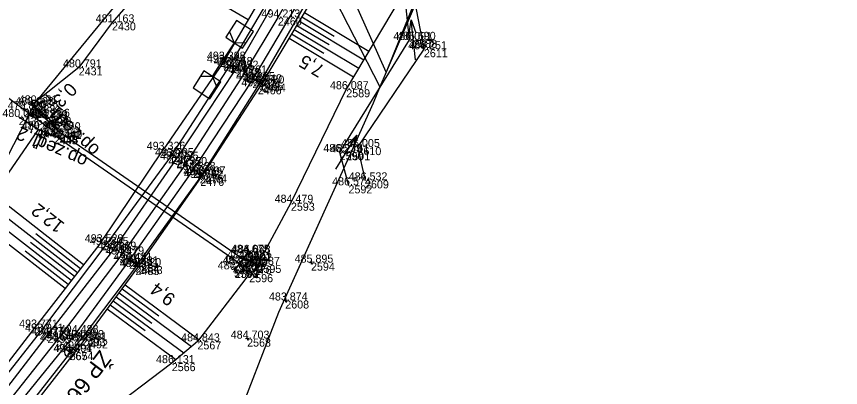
# Model space of a CAD drawing. Extents: x -1234191 to 23050, y -1290331 to -741191.
# Drawn here: x -864731.5 to -864608, y -1102915.1 to -1102859.5 of the extents above; entities that cross this region are included whole.
import ezdxf

# ---------------------------------------------------------------- set-up
doc = ezdxf.new("R2010")
doc.units = 0
for name, color, linetype in [('Vrstva 1', 7, 'Continuous'), ('Vrstva 13', 7, 'Continuous'), ('Vrstva 19', 7, 'Continuous'), ('Vrstva 4', 7, 'Continuous'), ('Vrstva 48', 7, 'Continuous'), ('Vrstva 49', 7, 'Continuous'), ('Vrstva 50', 7, 'Continuous'), ('Vrstva 53', 7, 'Continuous'), ('Vrstva 55', 7, 'Continuous'), ('Vrstva 58', 7, 'Continuous'), ('Vrstva 60', 7, 'Continuous'), ('Vrstva 61', 7, 'Continuous'), ('Vrstva 63', 7, 'Continuous'), ('Vrstva 7', 7, 'Continuous')]:
    doc.layers.add(name, color=color, linetype=linetype)

msp = doc.modelspace()

# ---------------------------------------------------------------- linework, layer by layer
at = {"layer": 'Vrstva 1'}
msp.add_lwpolyline([(-864682.21, -1102841.27), (-864687.29, -1102850.82), (-864692.33, -1102859.68), (-864697.4, -1102868.06), (-864706.3, -1102881.78), (-864715.74, -1102895.17), (-864725.57, -1102908.17), (-864735.83, -1102921.05), (-864737.97, -1102923.69), (-864746.17, -1102933.69), (-864756.55, -1102946.22), (-864772.27, -1102965.21), (-864787.36, -1102983.61), (-864800.07, -1102999.57)], dxfattribs=at)
at = {"layer": 'Vrstva 13'}
for p, q in [((-864724.79, -1102874.28), (-864726.15, -1102875.74)), ((-864727.28, -1102874.75), (-864726.88, -1102874.55)), ((-864727.28, -1102874.75), (-864727.2, -1102874.76)), ((-864727.2, -1102874.76), (-864725.27, -1102876.56)), ((-864727.85, -1102878.83), (-864727.06, -1102877))]:
    msp.add_line(p, q, dxfattribs=at)
for points in [[(-864725.27, -1102876.56), (-864725.35, -1102876.68), (-864727.28, -1102874.75)], [(-864727.2, -1102874.76), (-864726.88, -1102874.55), (-864725.27, -1102876.56), (-864725.35, -1102876.68)], [(-864726.03, -1102875.17), (-864726.15, -1102875.74), (-864725.59, -1102875.58)], [(-864725.94, -1102877.48), (-864728.29, -1102876.47), (-864728.3, -1102876.41), (-864725.85, -1102877.35), (-864725.94, -1102877.48)], [(-864726.98, -1102877.57), (-864727.06, -1102877), (-864727.53, -1102877.34)]]:
    msp.add_lwpolyline(points, dxfattribs=at)
at = {"layer": 'Vrstva 19'}
for p, q in [((-864766.6, -1102846.79), (-864725.6, -1102877.02)), ((-864725.35, -1102876.68), (-864725.27, -1102876.56)), ((-864697.57, -1102895.85), (-864725.35, -1102876.68)), ((-864725.35, -1102876.68), (-864725.35, -1102876.69)), ((-864697.57, -1102895.85), (-864725.35, -1102876.69)), ((-864725.85, -1102877.35), (-864725.94, -1102877.48)), ((-864698.11, -1102896.53), (-864725.85, -1102877.35)), ((-864725.85, -1102877.35), (-864725.85, -1102877.36)), ((-864698.1, -1102896.53), (-864725.85, -1102877.36)), ((-864696.79, -1102894.98), (-864698.81, -1102897.48)), ((-864698.8, -1102897.48), (-864696.79, -1102894.98)), ((-864696.79, -1102894.98), (-864696.79, -1102894.98)), ((-864698.11, -1102896.53), (-864698.21, -1102896.68)), ((-864698.11, -1102896.53), (-864698.1, -1102896.53)), ((-864696.63, -1102898.12), (-864698.11, -1102896.53)), ((-864698.1, -1102896.53), (-864697.57, -1102895.85)), ((-864697.49, -1102895.77), (-864697.57, -1102895.85)), ((-864697.57, -1102895.85), (-864697.57, -1102895.85)), ((-864697.57, -1102895.85), (-864695.39, -1102896.73)), ((-864695.39, -1102896.73), (-864697.49, -1102895.77)), ((-864698.81, -1102897.48), (-864698.8, -1102897.48)), ((-864698.21, -1102896.68), (-864696.63, -1102898.12))]:
    msp.add_line(p, q, dxfattribs=at)
for points in [[(-864725.27, -1102876.56), (-864725.94, -1102877.48)], [(-864725.85, -1102877.36), (-864725.35, -1102876.69)], [(-864697.49, -1102895.77), (-864696.91, -1102894.9), (-864696.79, -1102894.98)], [(-864698.21, -1102896.68), (-864698.92, -1102897.39), (-864698.8, -1102897.48)]]:
    msp.add_lwpolyline(points, dxfattribs=at)
at = {"layer": 'Vrstva 4'}
for points in [[(-864718.08, -1102893.74), (-864708.31, -1102880.42), (-864699.48, -1102866.8), (-864689.49, -1102849.9), (-864680.3, -1102831.93)], [(-864819.07, -1103021.91), (-864810.52, -1103010.02), (-864801.81, -1102998.6), (-864788.83, -1102982.45), (-864773.71, -1102964.13), (-864757.66, -1102945.31), (-864747.28, -1102932.75), (-864736.85, -1102920.15), (-864726.88, -1102907.24), (-864716.92, -1102894.44), (-864707.57, -1102880.97), (-864698.6, -1102867.35), (-864688.65, -1102850.07), (-864679.31, -1102832.31)], [(-864722.59, -1102906.94), (-864714.62, -1102896.1), (-864705.04, -1102882.52), (-864696.16, -1102869.06), (-864685.87, -1102851.67), (-864676.73, -1102833.65)], [(-864713.68, -1102897.05), (-864703.97, -1102883.7), (-864695.35, -1102869.99), (-864684.84, -1102851.86), (-864675.87, -1102834.17)], [(-864748.12, -1102932.02), (-864737.77, -1102919.21), (-864727.89, -1102906.72), (-864718.08, -1102893.74)], [(-864713.68, -1102897.05), (-864721.76, -1102907.69)], [(-864771.24, -1102966.15), (-864755.24, -1102946.97), (-864745.12, -1102934.48), (-864734.72, -1102921.84), (-864722.59, -1102906.94)], [(-864743.68, -1102935.62), (-864733.15, -1102922.25), (-864721.76, -1102907.69)]]:
    msp.add_lwpolyline(points, dxfattribs=at)
at = {"layer": 'Vrstva 48'}
for p, q in [((-864696.78, -1102860.02), (-864710.06, -1102852.26)), ((-864688.35, -1102858.93), (-864678.69, -1102864.71)), ((-864689.12, -1102860.22), (-864679.45, -1102866)), ((-864688.74, -1102859.57), (-864683.9, -1102862.46)), ((-864689.89, -1102861.5), (-864680.22, -1102867.29)), ((-864689.51, -1102860.86), (-864684.67, -1102863.75)), ((-864690.66, -1102862.79), (-864680.98, -1102868.58)), ((-864690.28, -1102862.15), (-864685.44, -1102865.04)), ((-864728.5, -1102873.38), (-864728.58, -1102873.49)), ((-864727.89, -1102873.81), (-864727.97, -1102873.92)), ((-864727.29, -1102874.25), (-864727.49, -1102874.54)), ((-864729.72, -1102875.55), (-864729.7, -1102875.53)), ((-864729.08, -1102875.95), (-864729.08, -1102875.94)), ((-864728.45, -1102876.36), (-864728.43, -1102876.32)), ((-864721.48, -1102896.72), (-864735.05, -1102886.16)), ((-864722.4, -1102897.9), (-864735.69, -1102887.57)), ((-864723.32, -1102899.09), (-864736.33, -1102888.97)), ((-864724.24, -1102900.27), (-864736.96, -1102890.38)), ((-864721.94, -1102897.31), (-864728.65, -1102892.09)), ((-864722.86, -1102898.49), (-864729.43, -1102893.38)), ((-864723.78, -1102899.68), (-864730.21, -1102894.68)), ((-864715.26, -1102899.71), (-864704.17, -1102907.88)), ((-864716.15, -1102900.92), (-864705.28, -1102908.93)), ((-864715.7, -1102900.31), (-864710.2, -1102904.37)), ((-864717.48, -1102902.73), (-864712.26, -1102906.57)), ((-864717.04, -1102902.12), (-864706.46, -1102909.92)), ((-864716.59, -1102901.52), (-864711.23, -1102905.47)), ((-864717.93, -1102903.33), (-864707.64, -1102910.92))]:
    msp.add_line(p, q, dxfattribs=at)
at = {"layer": 'Vrstva 49'}
for p, q in [((-864729.28, -1102872.81), (-864727.28, -1102874.75)), ((-864730.22, -1102873.59), (-864730.58, -1102873.24)), ((-864730.22, -1102873.24), (-864730.58, -1102873.59)), ((-864728.3, -1102876.41), (-864731.2, -1102874.59)), ((-864687.13, -1102896.34), (-864687.62, -1102896.43)), ((-864687.42, -1102896.14), (-864687.33, -1102896.63)), ((-864690.98, -1102902.01), (-864691.47, -1102902.1)), ((-864691.27, -1102901.81), (-864691.18, -1102902.3)), ((-864697, -1102907.53), (-864696.91, -1102908.02)), ((-864696.71, -1102907.73), (-864697.2, -1102907.81))]:
    msp.add_line(p, q, dxfattribs=at)
for points in [[(-864681.8, -1102831.96), (-864690.53, -1102849.31), (-864700.52, -1102866.44), (-864709.56, -1102879.49)], [(-864696.65, -1102832.92), (-864706.57, -1102848.27), (-864717.21, -1102860.41), (-864722.2, -1102867.15), (-864729.28, -1102872.81)], [(-864713.19, -1102896.91), (-864703.54, -1102883.19), (-864694.72, -1102869.57), (-864684.76, -1102852.92), (-864675.25, -1102834.44)], [(-864673.84, -1102856.53), (-864682.08, -1102870.42), (-864690.38, -1102887.42), (-864695.39, -1102896.73)], [(-864727.28, -1102874.75), (-864726.88, -1102874.55), (-864729.28, -1102872.81)], [(-864728.3, -1102876.41), (-864728.29, -1102876.47), (-864731.2, -1102874.59)], [(-864726.88, -1102874.55), (-864725.27, -1102876.56), (-864725.94, -1102877.48), (-864728.29, -1102876.47)], [(-864728.29, -1102876.47), (-864735.05, -1102886.17), (-864740.93, -1102899.13), (-864750.93, -1102912.52)], [(-864718.85, -1102893.34), (-864709.56, -1102879.49)], [(-864718.85, -1102893.34), (-864728.78, -1102906.11), (-864738.85, -1102919.08)], [(-864695.39, -1102896.73), (-864697.49, -1102895.77), (-864696.91, -1102894.9), (-864696.79, -1102894.98), (-864696.79, -1102894.98), (-864698.81, -1102897.48), (-864698.8, -1102897.48), (-864698.92, -1102897.39), (-864698.21, -1102896.68), (-864696.63, -1102898.12)], [(-864743.11, -1102936.38), (-864733.13, -1102923.08), (-864721.39, -1102908.03), (-864713.19, -1102896.91)], [(-864696.63, -1102898.12), (-864704.4, -1102908.18), (-864708.25, -1102911.44), (-864718.78, -1102919.45)]]:
    msp.add_lwpolyline(points, dxfattribs=at)
at = {"layer": 'Vrstva 50'}
for points in [[(-864673.32, -1102856.72), (-864672.67, -1102863.05), (-864683.08, -1102879.83)], [(-864671.84, -1102857.18), (-864670.44, -1102864.43)], [(-864670.44, -1102864.43), (-864680.4, -1102879.09), (-864679.27, -1102884.07)], [(-864683.08, -1102879.83), (-864681.75, -1102884.82)]]:
    msp.add_lwpolyline(points, dxfattribs=at)
at = {"layer": 'Vrstva 53'}
msp.add_line((-864728.85, -1102872.59), (-864728.81, -1102872.5), dxfattribs=at)
for points in [[(-864635.49, -1102733.5), (-864648.81, -1102800.46), (-864672.22, -1102858.78), (-864676.09, -1102867.88), (-864682.21, -1102854.19), (-864688.16, -1102846.44), (-864691.61, -1102825.91), (-864690.2, -1102823.4), (-864687.83, -1102820.97), (-864676.39, -1102798.67), (-864665.19, -1102755.33)], [(-864889.03, -1103323.28), (-864892.77, -1103263.78), (-864892.91, -1103184.37), (-864883.42, -1103119.48), (-864874.29, -1103087.16), (-864855.71, -1103052.53), (-864814.57, -1102995.09), (-864799.32, -1102988.77), (-864779.65, -1102957.8), (-864778.43, -1102951.42), (-864757.64, -1102926.36), (-864755.77, -1102924.22), (-864753.95, -1102921.47), (-864728.77, -1102872.58), (-864694.07, -1102830.31)], [(-864694.07, -1102830.31), (-864690.75, -1102847.15), (-864684.74, -1102855.05), (-864677.03, -1102870.08), (-864678.05, -1102872.49), (-864681.46, -1102880.03), (-864685.19, -1102888.26), (-864686.8, -1102891.82), (-864692.25, -1102903.86), (-864699.08, -1102921.54), (-864699.89, -1102923.65), (-864702.16, -1102929.53), (-864722.42, -1102960.74), (-864750.87, -1102982.07), (-864779.87, -1103011.49)]]:
    msp.add_lwpolyline(points, dxfattribs=at)
msp.add_circle((-864728.83, -1102872.54), 0.499, dxfattribs=at)
at = {"layer": 'Vrstva 55'}
for points in [[(-864685.34, -1102369.7), (-864652.19, -1102431.45), (-864635.26, -1102468.98), (-864625.8, -1102502.03), (-864631.68, -1102514.84), (-864613.23, -1102518.45), (-864607.97, -1102568.96), (-864611.13, -1102641.68), (-864611.4, -1102663.26), (-864622.78, -1102711.51), (-864635.49, -1102733.5), (-864648.81, -1102800.46), (-864676.09, -1102867.88), (-864677.03, -1102870.08)], [(-864677.03, -1102870.08), (-864678.05, -1102872.49), (-864681.46, -1102880.03), (-864685.19, -1102888.26), (-864692.25, -1102903.86), (-864699.08, -1102921.54), (-864702.16, -1102929.53), (-864722.42, -1102960.74), (-864750.87, -1102982.07), (-864779.87, -1103011.49), (-864808.83, -1103051.1), (-864846.52, -1103114.38), (-864836.8, -1103132.5), (-864838.87, -1103147.22), (-864863.34, -1103166.58), (-864871.29, -1103216.08), (-864869.74, -1103303.4), (-864855.1, -1103331.53)]]:
    msp.add_lwpolyline(points, dxfattribs=at)
at = {"layer": 'Vrstva 58'}
for p, q in [((-864671.72, -1102866), (-864672.34, -1102860.03)), ((-864683.66, -1102882.4), (-864680.48, -1102877.32))]:
    msp.add_line(p, q, dxfattribs=at)
for points in [[(-864672.63, -1102862.07), (-864672.34, -1102860.03), (-864671.64, -1102861.97)], [(-864681.97, -1102878.75), (-864680.48, -1102877.32), (-864681.12, -1102879.28)]]:
    msp.add_lwpolyline(points, dxfattribs=at)
at = {"layer": 'Vrstva 60'}
for p, q in [((-864717.21, -1102860.41), (-864717.21, -1102860.41)), ((-864692.33, -1102859.68), (-864692.33, -1102859.68)), ((-864672.67, -1102863.05), (-864672.67, -1102863.05)), ((-864672.03, -1102863.02), (-864672.03, -1102863.02)), ((-864670.44, -1102864.43), (-864670.44, -1102864.43)), ((-864700.53, -1102865.99), (-864700.53, -1102865.99)), ((-864700.52, -1102866.44), (-864700.52, -1102866.44)), ((-864699.48, -1102866.8), (-864699.48, -1102866.8)), ((-864722.2, -1102867.15), (-864722.2, -1102867.15)), ((-864698.6, -1102867.35), (-864698.6, -1102867.35)), ((-864697.4, -1102868.06), (-864697.4, -1102868.06)), ((-864696.16, -1102869.06), (-864696.16, -1102869.06)), ((-864695.08, -1102869.38), (-864695.08, -1102869.38)), ((-864695.35, -1102869.99), (-864695.35, -1102869.99)), ((-864694.72, -1102869.57), (-864694.72, -1102869.57)), ((-864682.08, -1102870.42), (-864682.08, -1102870.42)), ((-864729.28, -1102872.81), (-864729.28, -1102872.81)), ((-864728.83, -1102872.54), (-864728.83, -1102872.54)), ((-864730.4, -1102873.42), (-864730.4, -1102873.42)), ((-864731.2, -1102874.59), (-864731.2, -1102874.59)), ((-864727.28, -1102874.75), (-864727.28, -1102874.75)), ((-864727.2, -1102874.76), (-864727.2, -1102874.76)), ((-864726.88, -1102874.55), (-864726.88, -1102874.55)), ((-864728.3, -1102876.41), (-864728.3, -1102876.41)), ((-864728.29, -1102876.47), (-864728.29, -1102876.47)), ((-864725.35, -1102876.68), (-864725.35, -1102876.68)), ((-864725.35, -1102876.69), (-864725.35, -1102876.69)), ((-864725.27, -1102876.56), (-864725.27, -1102876.56)), ((-864725.94, -1102877.48), (-864725.94, -1102877.48)), ((-864725.85, -1102877.35), (-864725.85, -1102877.35)), ((-864725.85, -1102877.36), (-864725.85, -1102877.36)), ((-864680.4, -1102879.09), (-864680.4, -1102879.09)), ((-864709.56, -1102879.49), (-864709.56, -1102879.49)), ((-864708.31, -1102880.42), (-864708.31, -1102880.42)), ((-864683.08, -1102879.83), (-864683.08, -1102879.83)), ((-864682.07, -1102879.86), (-864682.07, -1102879.86)), ((-864707.57, -1102880.97), (-864707.57, -1102880.97)), ((-864706.3, -1102881.78), (-864706.3, -1102881.78)), ((-864705.04, -1102882.52), (-864705.04, -1102882.52)), ((-864704.05, -1102883.33), (-864704.05, -1102883.33)), ((-864703.97, -1102883.7), (-864703.97, -1102883.7)), ((-864703.54, -1102883.19), (-864703.54, -1102883.19)), ((-864679.27, -1102884.07), (-864679.27, -1102884.07)), ((-864681.75, -1102884.82), (-864681.75, -1102884.82)), ((-864690.38, -1102887.42), (-864690.38, -1102887.42)), ((-864718.85, -1102893.34), (-864718.85, -1102893.34)), ((-864718.08, -1102893.74), (-864718.08, -1102893.74)), ((-864716.92, -1102894.44), (-864716.92, -1102894.44)), ((-864715.74, -1102895.17), (-864715.74, -1102895.17)), ((-864696.91, -1102894.9), (-864696.91, -1102894.9)), ((-864696.79, -1102894.98), (-864696.79, -1102894.98)), ((-864696.79, -1102894.98), (-864696.79, -1102894.98)), ((-864714.62, -1102896.1), (-864714.62, -1102896.1)), ((-864698.11, -1102896.53), (-864698.11, -1102896.53)), ((-864698.1, -1102896.53), (-864698.1, -1102896.53)), ((-864697.57, -1102895.85), (-864697.57, -1102895.85)), ((-864697.57, -1102895.85), (-864697.57, -1102895.85)), ((-864697.49, -1102895.77), (-864697.49, -1102895.77)), ((-864687.37, -1102896.39), (-864687.37, -1102896.39)), ((-864713.68, -1102896.65), (-864713.68, -1102896.65)), ((-864713.68, -1102897.05), (-864713.68, -1102897.05)), ((-864713.19, -1102896.91), (-864713.19, -1102896.91)), ((-864698.92, -1102897.39), (-864698.92, -1102897.39)), ((-864698.81, -1102897.48), (-864698.81, -1102897.48)), ((-864698.8, -1102897.48), (-864698.8, -1102897.48)), ((-864698.21, -1102896.68), (-864698.21, -1102896.68)), ((-864695.39, -1102896.73), (-864695.39, -1102896.73)), ((-864696.63, -1102898.12), (-864696.63, -1102898.12)), ((-864691.23, -1102902.06), (-864691.23, -1102902.06)), ((-864728.78, -1102906.11), (-864728.78, -1102906.11)), ((-864727.89, -1102906.72), (-864727.89, -1102906.72)), ((-864726.88, -1102907.24), (-864726.88, -1102907.24)), ((-864722.59, -1102906.94), (-864722.59, -1102906.94)), ((-864721.76, -1102907.69), (-864721.76, -1102907.69)), ((-864725.57, -1102908.17), (-864725.57, -1102908.17)), ((-864721.39, -1102908.03), (-864721.39, -1102908.03)), ((-864704.4, -1102908.18), (-864704.4, -1102908.18)), ((-864696.95, -1102907.77), (-864696.95, -1102907.77)), ((-864723.6, -1102909.79), (-864723.6, -1102909.79)), ((-864723.55, -1102909.79), (-864723.55, -1102909.79)), ((-864708.25, -1102911.44), (-864708.25, -1102911.44))]:
    msp.add_line(p, q, dxfattribs=at)
at = {"layer": 'Vrstva 63'}
msp.add_line((-864723.6, -1102909.79), (-864723.5, -1102909.79), dxfattribs=at)
msp.add_circle((-864723.55, -1102909.79), 0.756, dxfattribs=at)
at = {"layer": 'Vrstva 7'}
for p, q in [((-864698.9, -1102863.47), (-864700.53, -1102865.99)), ((-864702.16, -1102868.5), (-864700.53, -1102865.99)), ((-864700.11, -1102866.26), (-864700.95, -1102865.71)), ((-864700.95, -1102865.71), (-864700.11, -1102866.26)), ((-864694.65, -1102869.64), (-864695.51, -1102869.12)), ((-864694.82, -1102868.95), (-864695.34, -1102869.81)), ((-864703.77, -1102882.92), (-864704.34, -1102883.74)), ((-864703.65, -1102883.62), (-864704.46, -1102883.04)), ((-864713.28, -1102896.95), (-864714.08, -1102896.34)), ((-864713.38, -1102896.25), (-864713.98, -1102897.04)), ((-864723.21, -1102910.1), (-864723.99, -1102909.48)), ((-864723.29, -1102909.4), (-864723.91, -1102910.18))]:
    msp.add_line(p, q, dxfattribs=at)
for points in [[(-864698.9, -1102863.47), (-864697.64, -1102864.29), (-864696, -1102861.77), (-864698.52, -1102860.14), (-864700.15, -1102862.65), (-864698.9, -1102863.47)], [(-864699.61, -1102861.81), (-864698.9, -1102863.47), (-864697.09, -1102863.44)], [(-864702.16, -1102868.5), (-864703.42, -1102867.69), (-864705.05, -1102870.2), (-864702.53, -1102871.84), (-864700.9, -1102869.32), (-864702.16, -1102868.5)], [(-864701.45, -1102870.16), (-864702.16, -1102868.5), (-864703.96, -1102868.53)]]:
    msp.add_lwpolyline(points, dxfattribs=at)

# ---------------------------------------------------------------- texts
at = {"layer": 'Vrstva 13'}
for s, rotation, p in [('1,2', 137.1166, (-864724.44, -1102873.62)), ('op.zeď', 137.1166, (-864718.93, -1102879.26)), ('1,2', 156.6954, (-864727.56, -1102877.44)), ('op.zeď', 156.6954, (-864720.7, -1102880.49))]:
    msp.add_text(s, height=2, rotation=rotation, dxfattribs=at).set_placement(p)
at = {"layer": 'Vrstva 48'}
for s, rotation, p in [('7,5', 149.3258, (-864685.18, -1102867.06)), ('0,3', 225.9735, (-864723.69, -1102869.28)), ('12,2', 142.1331, (-864724.18, -1102890.57)), ('9,4', 142.3358, (-864707.53, -1102901.48))]:
    msp.add_text(s, height=2, rotation=rotation, dxfattribs=at).set_placement(p)
at = {"layer": 'Vrstva 60'}
for s, p in [('2430', (-864717.21, -1102861.61)), ('2460', (-864692.33, -1102860.88)), ('2587', (-864672.67, -1102864.25)), ('2588', (-864672.03, -1102864.22)), ('2611', (-864670.44, -1102865.63)), ('2471', (-864700.53, -1102867.19)), ('2470', (-864700.52, -1102867.64)), ('2469', (-864699.48, -1102868)), ('2431', (-864722.2, -1102868.35)), ('2468', (-864698.6, -1102868.55)), ('2462', (-864697.4, -1102869.27)), ('2467', (-864696.16, -1102870.26)), ('2465', (-864695.08, -1102870.58)), ('2466', (-864695.35, -1102871.19)), ('2464', (-864694.72, -1102870.77)), ('2589', (-864682.08, -1102871.62)), ('2433', (-864729.28, -1102874.01)), ('2432', (-864728.83, -1102873.74)), ('2434', (-864730.4, -1102874.62)), ('2435', (-864731.2, -1102875.79)), ('2437', (-864727.28, -1102875.95)), ('2438', (-864727.2, -1102875.96)), ('2439', (-864726.88, -1102875.75)), ('2447', (-864728.3, -1102877.61)), ('2446', (-864728.29, -1102877.67)), ('2442', (-864725.35, -1102877.88)), ('2441', (-864725.35, -1102877.89)), ('2440', (-864725.27, -1102877.76)), ('2445', (-864725.94, -1102878.68)), ('2443', (-864725.85, -1102878.55)), ('2444', (-864725.85, -1102878.56)), ('2610', (-864680.4, -1102880.29)), ('2480', (-864709.56, -1102880.69)), ('2479', (-864708.31, -1102881.62)), ('2590', (-864683.08, -1102881.03)), ('2591', (-864682.07, -1102881.06)), ('2478', (-864707.57, -1102882.17)), ('2472', (-864706.3, -1102882.98)), ('2477', (-864705.04, -1102883.72)), ('2475', (-864704.05, -1102884.53)), ('2476', (-864703.97, -1102884.9)), ('2474', (-864703.54, -1102884.39)), ('2609', (-864679.27, -1102885.27)), ('2592', (-864681.75, -1102886.02)), ('2593', (-864690.38, -1102888.62)), ('2489', (-864718.85, -1102894.54)), ('2488', (-864718.08, -1102894.94)), ('2487', (-864716.92, -1102895.64)), ('2481', (-864715.74, -1102896.37)), ('5701', (-864696.91, -1102896.1)), ('2601', (-864696.79, -1102896.18)), ('2602', (-864696.79, -1102896.18)), ('2486', (-864714.62, -1102897.3)), ('2604', (-864698.11, -1102897.73)), ('2605', (-864698.1, -1102897.73)), ('2606', (-864697.57, -1102897.05)), ('2607', (-864697.57, -1102897.05)), ('2600', (-864697.49, -1102896.97)), ('2594', (-864687.37, -1102897.59)), ('2484', (-864713.68, -1102897.85)), ('2485', (-864713.68, -1102898.25)), ('2483', (-864713.19, -1102898.11)), ('5700', (-864698.92, -1102898.59)), ('2597', (-864698.81, -1102898.68)), ('2598', (-864698.8, -1102898.68)), ('2599', (-864698.21, -1102897.88)), ('2595', (-864695.39, -1102897.93)), ('2596', (-864696.63, -1102899.32)), ('2608', (-864691.23, -1102903.26)), ('2497', (-864728.78, -1102907.31)), ('2496', (-864727.89, -1102907.92)), ('2495', (-864726.88, -1102908.44)), ('2494', (-864722.59, -1102908.14)), ('2493', (-864721.76, -1102908.89)), ('2490', (-864725.57, -1102909.37)), ('2492', (-864721.39, -1102909.23)), ('2567', (-864704.4, -1102909.38)), ('2568', (-864696.95, -1102908.97)), ('2674', (-864723.6, -1102910.99)), ('665', (-864723.55, -1102910.99)), ('2566', (-864708.25, -1102912.64))]:
    msp.add_text(s, height=1.2, dxfattribs=at).set_placement(p)
at = {"layer": 'Vrstva 61'}
for s, p in [('481.163', (-864719.66, -1102860.41)), ('494.213', (-864694.79, -1102859.68)), ('486.091', (-864675.02, -1102863.05)), ('485.690', (-864674.48, -1102863.02)), ('486.251', (-864672.79, -1102864.43)), ('493.398', (-864702.98, -1102865.99)), ('493.445', (-864702.98, -1102866.44)), ('493.658', (-864701.93, -1102866.8)), ('480.791', (-864724.56, -1102867.15)), ('494.052', (-864701.05, -1102867.35)), ('494.261', (-864699.76, -1102868.06)), ('494.265', (-864698.61, -1102869.06)), ('493.708', (-864697.81, -1102869.99)), ('494.040', (-864697.53, -1102869.38)), ('493.580', (-864697.17, -1102869.57)), ('486.087', (-864684.53, -1102870.42)), ('480.003', (-864731.73, -1102872.81)), ('480.531', (-864731.19, -1102872.54)), ('479.820', (-864732.85, -1102873.42)), ('480.058', (-864733.65, -1102874.59)), ('480.219', (-864729.66, -1102874.76)), ('479.881', (-864729.63, -1102874.75)), ('480.266', (-864729.33, -1102874.55)), ('479.906', (-864730.75, -1102876.41)), ('480.277', (-864730.74, -1102876.47)), ('479.983', (-864727.81, -1102876.68)), ('481.383', (-864727.81, -1102876.69)), ('481.950', (-864727.72, -1102876.56)), ('481.855', (-864728.4, -1102877.48)), ('479.956', (-864728.3, -1102877.35)), ('481.356', (-864728.3, -1102877.36)), ('486.005', (-864682.85, -1102879.09)), ('493.326', (-864712.01, -1102879.49)), ('493.705', (-864710.76, -1102880.42)), ('486.233', (-864685.53, -1102879.83)), ('485.741', (-864684.43, -1102879.86)), ('494.095', (-864710.02, -1102880.97)), ('494.350', (-864708.75, -1102881.78)), ('494.328', (-864707.49, -1102882.52)), ('494.019', (-864706.51, -1102883.33)), ('493.682', (-864706.42, -1102883.7)), ('493.607', (-864705.99, -1102883.19)), ('486.532', (-864681.72, -1102884.07)), ('486.574', (-864684.2, -1102884.82)), ('484.479', (-864692.83, -1102887.42)), ('493.529', (-864721.3, -1102893.34)), ('493.805', (-864720.54, -1102893.74)), ('494.269', (-864719.37, -1102894.44)), ('494.479', (-864718.2, -1102895.17)), ('484.675', (-864699.37, -1102894.9)), ('485.088', (-864699.24, -1102894.98)), ('484.688', (-864699.24, -1102894.98)), ('494.431', (-864716.98, -1102896.1)), ('482.525', (-864700.56, -1102896.53)), ('484.195', (-864700.56, -1102896.53)), ('484.224', (-864700.02, -1102895.85)), ('482.554', (-864700.02, -1102895.85)), ('484.615', (-864699.95, -1102895.77)), ('485.895', (-864689.83, -1102896.39)), ('494.231', (-864716.04, -1102896.65)), ('493.971', (-864716.04, -1102897.05)), ('493.820', (-864715.64, -1102896.91)), ('484.800', (-864701.37, -1102897.39)), ('485.113', (-864701.26, -1102897.48)), ('484.813', (-864701.25, -1102897.48)), ('484.597', (-864700.66, -1102896.68)), ('483.387', (-864697.84, -1102896.73)), ('483.176', (-864699.08, -1102898.12)), ('483.874', (-864693.68, -1102902.06)), ('493.771', (-864731.14, -1102906.11)), ('493.941', (-864730.25, -1102906.72)), ('494.378', (-864729.34, -1102907.24)), ('494.488', (-864725.04, -1102906.94)), ('494.608', (-864728.03, -1102908.17)), ('494.013', (-864724.21, -1102907.69)), ('493.801', (-864723.75, -1102908.03)), ('484.843', (-864706.85, -1102908.18)), ('484.703', (-864699.41, -1102907.77)), ('494.404', (-864726, -1102909.79)), ('494.391', (-864725.96, -1102909.79)), ('486.131', (-864710.61, -1102911.44))]:
    msp.add_text(s, height=1.2, dxfattribs=at).set_placement(p)
at = {"layer": 'Vrstva 63'}
msp.add_text('ŽP 665', height=2.4, rotation=232.9199, dxfattribs=at).set_placement((-864719.04, -1102909.35))

doc.saveas('drawing.dxf')
